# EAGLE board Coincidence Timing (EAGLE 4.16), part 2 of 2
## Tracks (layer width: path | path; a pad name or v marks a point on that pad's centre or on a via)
+1.2V  (via drill 0.51)
  Top 0.178: 111.12,40.64 IC15.2 | IC16.81 v97.41,91.31 97.41,91.19 97.79,90.81 97.79,85.98 99.44,85.98 | v80.77,91.31 80.83,91 IC16.109 82.68,91.06 82.68,91.19 84.2,91.19 | v80.77,83.69 80.96,83.5 IC16.124 85.03,83.5 85.6,82.93 | v80.77,79.76 81.03,79.76 81.28,80.01 IC16.131 84.84,80.01 85.6,80.77 85.6,82.93 | v104.65,73.28 103.39,73.28 IC16.37 102.62,73.41 102.62,73.28 101.09,73.28 | v104.65,80.14 104.52,80.01 IC16.50 | v104.65,86.11 104.65,85.98 103.19,85.98 IC16.62 102.49,85.98 99.44,85.98 | 84.2,91.19 84.33,91.31 84.33,92.08 IC16.107 | 84.2,91.19 84.33,91.06 84.33,89.53 86.74,87.12 86.74,82.93 85.6,82.93 | 101.09,73.28 100.97,73.15 100.97,72.39 IC16.35 100.97,71.12 100.97,69.72 v100.46,69.22 100.71,68.83 105.79,63.75 105.79,52.58 C85.+ | 101.09,73.28 99.44,74.93 99.44,85.98 | IC16.26 96.41,70.63 v96.14,70.36
  Top 0.508: IC15.2 C82.2 | 106.43,51.56 C85.+ 106.43,50.55
  Top 0.635: 107.7,40.64 111.12,40.64 | 106.43,47.12 106.43,50.55
  Bottom 0.178: C83.2 79.5,80.01 79.63,79.88 v80.77,79.76 | C79.2 105.45,73.28 v104.65,73.28 104.27,73.53 103.63,73.53 102.74,74.42 100.58,74.42 100.58,78.23 102.23,79.88 104.27,79.88 v104.65,80.14 C78.2 | C80.2 105.58,86.11 v104.65,86.11 | v100.46,69.22 96.9,69.22 C77.2 96.52,69.98 v96.14,70.36 | C74.2 79.63,91.06 79.88,91.31 v80.77,91.31 81.15,90.81 86.74,90.81 87.76,89.79 97.03,89.79 C72.2 v97.41,91.31 | C76.2 79.76,83.44 80.01,83.69 v80.77,83.69
  pour Top (isolate 0.381): 76.2,33.02 76.2,48.26 107.95,48.26 107.95,33.02
+3.3V  (via drill 0.51)
  Top 0.178: R10.1 32.89,100.2 34.29,100.2 34.92,100.84 36.7,100.84 R14.1 v37.85,100.2 | 48.01,25.65 C81.2 | R42.1 32.38,62.61 32.89,62.1 34.29,62.1 34.92,62.74 36.7,62.74 R46.1 v37.85,62.1 | C5.2 IC2.8 19.68,84.07 19.81,84.2 v21.08,84.2 | C34.2 19.18,73.28 IC8.8 19.56,73.41 19.68,73.53 v21.08,73.53 | R12.1 v31.37,96.77 | R44.1 v31.37,58.67 | 29.34,59.56 L13.1 29.46,59.56 v29.46,58.42 | 29.34,59.56 29.46,59.69 | L10.2 v18.92,53.85 | L1.2 v18.92,92.33 | 24.98,95 L2.1 v26.16,94.87 | 29.34,59.56 29.34,59.44 | L3.1 33.62,89.95 v33.53,90.04 | L12.1 35.05,51.82 34.92,51.94 v33.53,51.94 | R40.1 v31.24,67.31 | R8.1 v31.11,105.41 | 25.69,107.61 L5.1 25.65,107.31 25.78,107.44 v24.38,107.44 | L15.1 v43.43,69.72 | 41.78,107.82 L6.1 v43.31,107.82 | L4.1 29.46,97.66 v29.46,96.52 | L11.1 v26.16,56.77 | L14.1 25.57,69.34 v24.38,69.34 | R57.2 v54.48,54.23 | R59.2 v62.1,54.23 | R27.2 v62.1,92.33 | R25.2 v54.48,92.33 | 58.67,108.58 58.67,108.71 58.65,108.71 IC6.32 58.65,108.58 58.67,108.58 | 58.67,108.58 v58.67,107.44 | 58.67,70.61 v58.67,69.34 | 63.75,66.29 63.7,66.29 IC12.22 63.75,66.18 63.75,66.17 63.7,66.22 IC12.23 63.96,66.8 v65.02,66.8 | IC6.22 63.63,104.28 63.63,104.27 63.7,104.34 IC6.23 63.75,104.93 63.75,104.9 63.88,104.78 v65.02,104.78 | 58.67,108.58 C29.2 | 58.67,70.61 58.65,70.61 IC12.32 | 58.67,70.61 C56.2 | IC6.13 v62.99,97.28 | IC12.13 v62.99,59.18 | 98.55,123.95 IC17.18 | 98.55,123.95 C88.2 | 98.55,123.95 96.52,123.95 96.01,123.44 IC17.20 92.91,122.12 91.69,120.9 91.69,120.14 | 89.15,119.38 89.09,119.38 IC18.6 89.53,119.51 90.17,120.14 91.69,120.14 | C90.2 89.11,119.42 89.15,119.38 | 91.69,120.14 91.69,120.23 R74.2 | 89.15,119.38 87.63,119.38 87.12,118.87 87.12,113.54 87.88,112.78 91.69,112.78 91.69,112.69 R76.2 91.57,111.63 91.69,111.51 v91.69,111.38
  Top 0.178: 99.44,92.78 IC16.77 99.44,92.08 99.44,91.57 v99.57,91.19 99.82,90.81 99.82,88.01 | 94.61,97.79 R68.2 v94.61,98.93 | IC16.84 95.91,91.29 v95.76,90.93 | v97.92,98.93 R67.2 | v86.87,94.36 86.87,94.23 86.91,94.19 IC16.102 | IC16.138 82.11,76.45 v80.77,76.45 | v80.77,87.76 80.9,87.5 IC16.116 | 82.12,82.04 IC16.127 83.02,82 v83.57,82.55 | IC16.5 85.85,71.69 v85.85,70.36 | C61.2 v94.87,70.36 94.87,71.71 IC16.23 95,72.39 95,73.28 97.66,73.28 97.79,73.15 97.79,72.64 97.92,72.64 97.92,72.39 IC16.29 | C86.2 125.22,72.39 MOD1.2-31 | 105.79,77.98 103.89,77.98 IC16.46 | 105.79,77.98 108.33,77.98 v108.71,78.36 109.6,78.36 110.24,77.72 110.24,75.44 v111.63,74.04 | 105.79,77.98 105.79,81.92 105.7,82 IC16.54 102.49,82.04 101.6,82.04 v101.6,82.42 | C63.1 IC13.8 IC13.7 87.76,62.61 87.76,62.23 87.5,62.23 87.5,62.1 85.72,62.1 85.72,61.98 v85.47,61.59 IC13.3 | R66.2B 97.79,57.15 97.54,57.15 R66.3B 97.03,56.64 v97.03,55.88 | 99.82,88.01 102.49,88.01 IC16.66 | v100.08,58.67 100.08,58.93 99.82,59.18 99.82,61.21 J3.4 | v90.42,94.23 v90.41,94.22 IC16.95 90.41,92.71 90.42,92.71 v90.42,91.19 | R70.2 v92.58,98.93 v89.41,98.93 | 99.82,88.01 99.82,87.88 v99.06,87.12
  Top 0.635: C84.+ 57.4,24.38 56.13,25.65 48.01,25.65 IC14.2 | v94.61,82.68 v94.61,86.36 | v87.88,84.84 v87.88,86.49
  Bottom 0.178: C68.2 99.44,91.06 arc-90 v99.57,91.19 99.31,91.57 99.31,92.33 95.25,92.33 | v95.76,90.93 95,90.93 | v97.92,98.93 94.74,98.93 94.61,98.81 | v108.71,78.36 108.2,78.87 106.17,78.87 106.17,78.36 C60.2 | v111.63,74.04 112.39,73.28 123.95,73.28 123.95,72.9 MOD1.2-31 | 101.6,82.04 95.25,82.04 v94.61,82.68 | 101.6,82.04 105.28,82.04 C59.2 | 95.25,55.88 v97.03,55.88 99.82,58.67 v100.08,58.67 | 95.25,59.82 99.69,59.82 J3.4 | 101.6,82.04 v101.6,82.42 | v99.06,87.12 98.93,87.25 95.12,87.25 95.12,86.87 v94.61,86.36
  Bottom 0.635: IC14.2 45.97,25.65 48.26,27.94 48.26,50.8
  pour Bottom: 17.78,114.3 17.78,49.53 95.25,49.53 95.25,106.68 107.95,106.68 107.95,124.46 82.55,124.46 82.55,114.3
+5V  (via drill 0.51, 0.71)
  Top 0.178: 48.01,28.19 C73.2 | L8.2 53.59,114.05 70.87,114.05 v70.87,109.73 | v70.87,95.5 70.61,95.25 L7.2 | 53.59,74.17 L17.2 v53.59,77.98 | v70.87,57.15 L16.2 | v68.33,77.98 v60.2,77.98 | FAN+.TP 12.45,11.43 C65.+ 12.45,12.45 20.32,20.32 29.21,20.32 29.21,21.34 32,24.13 NTC+.TP | 122.05,111 121.92,111 C89.2 122.05,111.76 122.17,111.51 122.83,110.84 | R73.2 127.51,113.79 R72.CCW | R72.CCW 127.25,113.79 | DIS.2 122.83,110.84 | 122.83,110.84 122.83,115.22 123.7,116.08 126.49,116.08 127.25,115.32 R72.CCW
  Top 0.508: IC15.3 C75.2
  Top 0.635: 64.77,22.86 63.5,22.86 C70.+ | 64.77,22.86 F1.1A | C70.+ 62.23,25.4 59.44,28.19 48.01,28.19 IC14.3 | v73.66,95.5 73.66,77.98 v68.33,77.98 | v70.87,69.85 70.1,69.85 v68.33,71.63 | v70.87,42.93 v70.87,51.05 | v112.01,45.47 IC15.3 | v83.06,104.65 83.82,103.89 85.09,103.89 87.38,106.17 89.15,106.17 92.96,102.36 v102.11,102.36 | DIS.2 122.83,106.93 122.94,106.93 120.9,104.9 118.62,104.9 116.08,102.36 v112.52,102.36 | v70.87,33.27 63.12,25.53 63.12,24.89 62.36,24.13 C70.+ | 64.77,22.86 64.77,18.54 62.48,16.26 62.48,14.22 D1.2 64.9,14.22
  Bottom 0.178: v70.87,95.5 v70.87,109.73 | v60.2,77.98 v53.59,77.98 | 42.93,27.94 43.18,27.94 | 42.93,27.94 IC14.3 | 42.93,27.94 39.37,27.94 36.7,25.27 31.88,25.27 31.88,24.13 NTC+.TP
  Bottom 0.508: 70.61,42.93 v70.87,42.93 71.12,42.93
  Bottom 0.635: v70.87,95.5 v73.66,95.5 v83.06,104.65 | v70.87,69.85 v70.87,57.15 v70.87,51.05 | v68.33,71.63 v68.33,77.98 | v70.87,33.27 v70.87,42.93 | v112.01,45.47 112.01,46.48 71.12,46.48 71.12,42.93 | v102.11,102.36 v112.52,102.36
/LATCH_EN  (via drill 0.51)
  Top 0.178: R7.2 40.39,94.65 v40.39,87.38 | v66.29,82.8 68.83,82.8 v68.83,88.9 | R39.2 42.2,56.68 v45.59,60.07 | v39.88,72.39 v39.88,75.69 | v45.59,70.1 v43.31,72.39 | v45.59,65.53 v45.59,68.07 | v45.47,82.8 v43.43,82.8 v52.32,82.8 | v101.73,91.31 101.73,89.41 102.49,89.41 IC16.69
  Bottom 0.178: v40.39,87.38 40.39,82.8 v43.43,82.8 | v52.32,82.8 v66.29,82.8 | v68.83,88.9 71.63,88.9 83.57,100.58 v85.34,100.58 85.72,100.33 89.15,100.33 93.22,96.27 100.97,96.27 100.97,92.08 v101.73,91.31 | v45.59,60.07 v45.59,65.53 | v43.31,72.39 v39.88,72.39 | v45.59,68.07 v45.59,70.1 | v39.88,75.69 39.88,77.22 v45.47,82.8
AGND  (via drill 0.51, 0.71, 1.07)
  Top 0.178: 26.54,65.44 IC10.15 26.44,65.46 26.44,65.63 26.42,65.66 26.42,62.1 | 22.35,61.47 22.35,62.23 22.38,62.26 IC7.13 | 20.07,59.94 20.95,59.94 | IC7.15 21.39,62.28 21.39,62.13 21.34,62.08 21.34,61.47 20.19,61.47 | IC1.4 20.09,98.04 | IC1.13 22.35,100.35 22.35,99.57 22.23,99.69 21.34,99.69 21.34,100.33 IC1.15 | IC1.1 20.83,99.57 | 20.83,98.04 20.07,98.04 IC1.4 | 26.42,100.2 26.42,103.76 26.44,103.73 IC4.15 | 26.92,100.2 26.92,103.76 26.95,103.73 IC4.14 | 26.92,62.1 26.92,65.66 26.95,65.63 26.95,65.46 IC10.14
  Bottom 0.178: C35.2 21.3,67.27 v21.21,67.18 | C6.2 21.3,105.37 v21.21,105.28 | C10.2 24.26,103.72 v24.26,105.03 24.26,106.01 C12.2 | C40.1 24.51,66.55 arc90 v24.26,66.8 24.26,67.91 C42.1 | C27.1 64.17,107.66 v64.01,107.82 | C57.1 64.17,69.56 v64.01,69.72 | C52.1 55.08,63.59 v55.88,64.39 56.68,63.59 C50.1 | C51.1 59.91,63.59 v60.83,64.52 61.76,63.59 C58.1 | C21.1 55.08,101.69 v55.88,102.49 56.68,101.69 C22.1 | C23.1 60.03,101.69 v60.96,102.62 61.89,101.69 C28.1 | C25.1 v57.78,104.9 | C53.1 v57.78,66.8 | C69.1 90.26,97.28 v88.9,97.28 88.86,97.24 C71.1 | C74.1 77.89,89.32 77.85,89.28 v77.85,89.41 77.89,89.37 C67.1 | 77.98,76.45 C64.1 77.85,76.45 77.85,80.01 C83.1 77.89,83.4 77.85,83.44 | v87,67.44 86.23,67.44 C62.1 | 77.85,83.44 v76.58,83.44 | C66.1 84.71,83.69 85.34,83.06 | 77.85,83.44 C76.1
  Bottom 0.635: v86.36,82.17 v85.98,83.69 85.34,83.06 v84.84,82.55 86.36,82.04
  other vias: 12.95,101.6 12.95,63.5 45.72,30.48 50.8,30.48 50.8,49.02 45.72,49.02 109.09,80.14 108.97,94.74 110.49,117.09 97.03,105.16 114.81,38.1 68.33,38.61 50.8,21.59 7.62,81.03 32.26,120.9 69.34,122.43 95,132.08 144.53,84.58 147.07,26.67 73.41,38.61 101.22,88.77 100.97,87.25 104.78,87.38 96.01,78.74 100.2,85.22 102.49,71.75 99.95,73.15 101.35,80.14 110.87,85.98 115.44,85.98 111.12,82.68 108.97,81.79
  pour Top (rank 2): 0,0 96.52,0 96.52,13.97 166.88,13.97 166.88,140.72 0,140.72
  pour Bottom (rank 2): 0,0 0,140.72 166.88,140.72 166.88,0
ARABBIT0  (via drill 0.51)
  Top 0.178: v108.71,88.01 108.71,84.96 103.89,84.96 IC16.60 | v119.51,89.28 124.21,89.28 124.21,88.9 MOD1.2-15
  Bottom 0.178: v108.71,88.01 109.98,89.28 v119.51,89.28
ARABBIT1  (via drill 0.51)
  Top 0.178: IC16.59 103.89,84.45 111.38,84.45 v114.94,88.01
  Bottom 0.178: v114.94,88.01 115.44,88.52 119.89,88.52 121.28,89.92 122.05,89.92 MOD1.2-14
ARABBIT2  (via drill 0.51)
  Top 0.178: v116.71,90.04 115.7,89.03 115.7,87.63 112.14,84.07 103.89,84.07 IC16.58
  Bottom 0.178: v116.71,90.04 117.98,91.31 124.21,91.31 124.21,90.93 MOD1.2-13
CAL_HI/LO  (via drill 0.51)
  Top 0.178: IC5.8 39.37,102.62 39.12,102.36 39.12,101.35 39.75,100.71 40.13,100.71 v41.91,98.93 | v41.91,86.49 v41.91,93.09 | v44.45,83.57 v53.34,83.57 | v67.31,83.57 68.07,83.57 v68.07,87.88 | IC11.8 38.99,64.52 v38.99,67.06 | 39.12,74.93 v39.12,74.8 v39.12,71.37 | IC16.144 80.61,73.5 v80.52,73.41 | v67.31,76.45 v69.34,76.45
  Bottom 0.178: v41.91,93.09 v41.91,98.93 | v41.91,86.49 41.91,83.57 v44.45,83.57 44.45,82.68 39.12,77.34 v39.12,74.8 | v53.34,83.57 v67.31,83.57 v67.31,76.45 | v68.07,87.88 71.37,87.88 83.31,99.57 v84.58,99.57 | v38.99,67.06 39.12,67.06 v39.12,71.37 | v80.52,73.41 72.39,73.41 v69.34,76.45
CALIBRATE  (via drill 0.51)
  Top 0.178: R49.1 37.17,68.58 v38.35,68.58 | v38.35,78.99 v47.24,78.99 | v72.64,93.98 v72.64,78.99 v61.21,78.99 | R17.1 38.44,106.77 v38.61,106.93 | v38.61,111.25 38.61,112.78 v40.39,114.55 | v38.35,72.39 v38.35,75.69 | IC16.143 81.19,74 81.03,74.17 v79.5,74.17 | v84.33,105.16 84.33,105.92 v79.5,110.74
  Bottom 0.178: v47.24,78.99 v61.21,78.99 | v72.64,93.98 73.41,93.98 84.33,104.65 v84.33,105.16 | v38.61,111.25 v38.61,106.93 | v38.35,75.69 v38.35,78.99 | v38.35,68.58 v38.35,72.39 | v40.39,114.55 75.69,114.55 v79.5,110.74 | v72.64,78.99 72.64,74.17 v79.5,74.17
CLK+
  Top 0.178: IC17.7 103.63,101.6 arc-90 103.12,101.09 93.85,101.09 arc90 93.6,100.84 93.6,96.39 arc-90 93.26,96.05 R70.1 | R70.1 92.58,96.01 92.46,96.01 92.46,92.8 IC16.91 | R71.2 91.31,96.01 92.54,96.01 R70.1
CLK-
  Top 0.178: IC16.90 92.91,94.44 arc-90 93.22,94.74 94.23,94.74 arc90 94.49,95 94.49,96.01 arc-180 94.49,96.05 R68.1 94.74,96.05 94.74,96.01 94.78,96.05 R69.2 96.43,96.05 arc90 96.77,96.39 96.77,99.82 arc-90 97.28,100.33 103.69,100.33 arc90 104.9,101.54 IC17.8
CLKA+
  Top 0.178: C17.1 59.18,92.33 arc180 R27.1 arc90 59.18,92.29 59.18,90.68 arc180 R28.2 arc-90 59.44,90.46 TP1A.TP
CLKA-
  Top 0.178: 57.4,92.33 arc-180 R25.1 arc180 57.4,92.33 | 57.4,92.33 C18.1 | 57.4,92.33 57.4,90.72 arc-90 R26.2 arc90 57.15,90.46 TP2A.TP
CLKB+
  Top 0.178: R59.1 59.31,54.23 59.31,55.54 arc90 C46.1 | R59.1 59.18,54.23 arc-180 R59.1 | R60.2 59.31,52.58 59.31,54.14 arc90 R59.1 | R60.2 59.18,52.58 arc-180 R60.2 | R60.2 arc-90 59.44,52.36 TP3A.TP
CLKB-
  Top 0.178: C47.1 57.4,54.23 arc-180 R57.1 arc-90 57.4,54.19 57.4,52.58 arc-180 R58.2 arc90 57.15,52.36 TP4A.TP
DA0  (via drill 0.51)
  Top 0.178: v69.22,111.76 65.79,111.76 R29.1B | v105.66,109.22 105.66,91.69 104.52,90.55 103.89,90.55 IC16.71
  Bottom 0.178: v69.22,111.76 76.83,111.76 78.99,109.6 92.71,109.6 93.34,110.24 104.65,110.24 v105.66,109.22
DA1  (via drill 0.51)
  Top 0.178: v70.1,111 65.79,111 R29.2B | v102.74,97.41 102.74,91.06 IC16.72
  Bottom 0.178: v70.1,111 70.23,110.87 77.09,110.87 80.9,107.06 88.65,107.06 94.87,100.84 99.31,100.84 v102.74,97.41
DA2  (via drill 0.51)
  Top 0.178: v79.63,107.19 71.75,107.19 69.72,109.22 69.72,110.24 65.79,110.24 R29.3B | v101.35,97.66 101.35,93.47 IC16.73
  Bottom 0.178: v79.63,107.19 80.14,106.68 88.52,106.68 94.74,100.46 98.55,100.46 v101.35,97.66
DA3  (via drill 0.51)
  Top 0.178: v72.01,106.43 69.34,109.09 69.34,109.35 65.79,109.35 R29.4B | v99.06,97.41 100.97,95.5 100.97,93.47 IC16.74
  Bottom 0.178: v72.01,106.43 72.14,106.3 88.39,106.3 94.61,100.08 98.42,100.08 99.06,99.44 v99.06,97.41
DA4  (via drill 0.51)
  Top 0.178: v81.92,92.84 81.92,93.85 77.47,98.3 77.47,105.66 70.1,105.66 R30.1B | v100.2,94.23 100.33,94.11 100.33,93.47 IC16.75
  Bottom 0.178: v81.92,92.84 82.3,93.22 99.19,93.22 v100.2,94.23
DA5  (via drill 0.51)
  Top 0.178: v81.03,93.6 77.09,97.54 77.09,104.9 70.1,104.9 R30.2B | v89.28,94.23 89.41,94.23 89.41,93.47 IC16.97
  Bottom 0.178: v81.03,93.6 88.65,93.6 v89.28,94.23
DA6  (via drill 0.51)
  Top 0.178: v76.33,104.14 70.1,104.14 R30.3B | v79.63,102.87 87.12,95.38 87.88,95.38 87.88,93.47 IC16.100
  Bottom 0.178: v76.33,104.14 77.6,102.87 v79.63,102.87
DA7  (via drill 0.51)
  Top 0.178: v73.41,103.25 70.1,103.25 R30.4B | v78.23,101.35 83.06,96.52 v83.06,92.33 | v87.38,91.31 87.5,91.44 87.5,92.08 IC16.101
  Bottom 0.178: v73.41,103.25 75.31,101.35 v78.23,101.35 | v83.06,92.33 84.07,91.31 v87.38,91.31
DA8  (via drill 0.51)
  Top 0.178: v78.99,89.53 74.93,93.6 74.93,98.68 68.83,98.68 68.83,101.47 69.22,101.47 R31.1B | v85.09,89.92 86.36,91.19 86.36,92.08 IC16.103
  Bottom 0.178: v78.99,89.53 79.38,89.92 v85.09,89.92
DA9  (via drill 0.51)
  Top 0.178: v79.12,94.36 76.71,96.77 76.71,100.84 70.1,100.84 R31.2B | v85.72,94.36 85.85,94.23 85.85,93.47 IC16.104
  Bottom 0.178: v79.12,94.36 v85.72,94.36
DA10
  Top 0.178: R31.3B 70.1,100.08 75.69,100.08 75.69,94.49 80.64,89.53 81.53,89.53 IC16.112
DA11
  Top 0.178: R31.4B 70.1,99.19 75.31,99.19 75.31,94.36 80.64,89.03 81.53,89.03 IC16.113
DAC-A  (via drill 0.51)
  Top 0.178: IC2.3 28.45,86.61 28.45,82.04 v33.53,82.04 | v42.42,82.04 v51.31,82.04 | v65.28,82.04 69.6,82.04 v69.6,89.92
  Bottom 0.178: v33.53,82.04 v42.42,82.04 | v51.31,82.04 v65.28,82.04 65.53,81.66 65.53,72.64 67.82,70.36 68.83,70.36 69.6,71.12 72.14,71.12 72.14,66.42 79.12,59.44 116.71,59.44 132.59,75.31 160.91,75.31 160.91,75.69 MOD1.1-27 | v69.6,89.92 72.01,89.92 83.95,101.6 v86.11,101.6
DAC-B  (via drill 0.51)
  Top 0.178: IC8.3 v26.29,75.95 | v39.37,79.76 v48.26,79.76 | v71.88,92.96 v71.88,84.07 71.88,79.76 v62.23,79.76
  Bottom 0.178: v26.29,75.95 28.83,79.76 v39.37,79.76 | v48.26,79.76 v62.23,79.76 | v71.88,92.96 73.15,92.96 84.96,104.52 v88.39,104.65 | v71.88,84.07 72.26,84.45 81.28,84.45 81.79,83.95 81.79,82.8 82.8,81.79 83.95,81.79 84.33,81.41 84.33,76.83 87,74.17 97.54,74.17 97.54,70.1 98.04,69.6 98.81,69.6 99.19,69.98 100.84,69.98 101.98,68.83 125.6,68.83 132.46,75.69 158.88,75.69 MOD1.1-28
DAC-CLK  (via drill 0.51)
  Top 0.178: IC8.1 27.43,73.41 27.43,80.52 | 27.43,80.52 27.43,84.07 IC2.1 | v31.5,80.52 27.43,80.52 | v49.28,80.52 v40.39,80.52 | v71.12,91.95 71.12,80.52 v63.25,80.52 | v81.28,107.82 81.79,107.31 81.79,104.14 83.06,102.87 85.85,102.87 85.85,103.25 86.49,103.89 87.25,103.89 v87.63,103.63
  Bottom 0.178: v40.39,80.52 v31.5,80.52 | v63.25,80.52 v49.28,80.52 | v71.12,91.95 72.77,91.95 84.71,103.63 v87.63,103.63 | v81.28,107.82 88.39,107.82 89.03,107.19 101.22,107.19 102.49,108.46 162.94,108.46 162.94,85.09 162.81,84.96 162.18,84.96 MOD1.1-19
DAC-D  (via drill 0.51)
  Top 0.178: IC8.2 23.11,74.68 22.61,75.18 22.61,84.71 23.24,85.34 IC2.2 27.94,85.34 27.94,81.28 v32.51,81.28 | v41.4,81.28 v50.29,81.28 | v64.26,81.28 70.36,81.28 v70.36,90.93 | v137.29,85.98 125.98,97.28 v106.43,97.28
  Bottom 0.178: v50.29,81.28 v64.26,81.28 | v70.36,90.93 72.39,90.93 84.33,102.62 v86.87,102.62 87.25,102.36 87.88,102.36 93.6,96.65 105.79,96.65 v106.43,97.28 | v137.29,85.98 144.4,85.98 145.03,85.34 160.91,85.34 160.91,85.72 MOD1.1-17 | v32.51,81.28 v41.4,81.28 v32.51,81.28
DATAREADY  (via drill 0.51)
  Top 0.178: v104.78,88.52 103.89,88.52 IC16.67
  Bottom 0.178: v104.78,88.52 106.05,87.25 115.57,87.25 116.33,86.49 122.05,86.49 MOD1.2-18
DB0  (via drill 0.51)
  Top 0.178: v65.79,86.36 58.67,79.25 58.67,76.45 63.25,76.45 64.9,74.8 64.9,74.04 R61.1B | IC16.114 79.48,88.5 77.34,86.36 v75.82,86.36
  Bottom 0.178: v65.79,86.36 v75.82,86.36
DB1  (via drill 0.51)
  Top 0.178: v65.41,84.84 59.05,78.49 59.05,76.83 64.01,76.83 66.55,74.3 66.55,73.03 65.79,73.03 R61.2B | v84.45,85.09 84.45,87.38 83.83,88 IC16.115
  Bottom 0.178: v65.41,84.84 84.33,84.84 v84.45,85.09
DB2
  Top 0.178: 74.3,78.23 74.3,77.34 71.75,77.34 66.67,72.26 65.79,72.26 R61.3B | 74.3,78.23 74.3,78.36 | IC16.118 81.53,86.49 80.77,86.49 74.3,80.01 74.3,78.23
DB3
  Top 0.178: R61.4B 65.79,71.5 67.06,71.5 67.06,72.14 71.88,76.96 74.68,76.96 74.68,79.88 80.77,85.98 81.53,85.98 IC16.119
DB4
  Top 0.178: R62.1B 70.1,67.69 70.36,67.69 71.88,69.22 71.88,76.45 72.01,76.58 75.06,76.58 75.06,79.76 80.26,84.96 81.53,84.96 IC16.121
DB5
  Top 0.178: R62.2B 70.1,66.8 70.36,66.8 72.26,68.71 72.26,76.2 75.44,76.2 75.44,79.63 80.26,84.45 81.53,84.45 IC16.122
DB6
  Top 0.178: R62.3B 69.6,66.02 69.6,66.04 70.48,66.04 72.64,68.2 72.64,75.82 75.82,75.82 75.82,79.5 79.25,82.94 81.42,82.94 81.47,83 IC16.125 | IC16.125 | IC16.125
DB7
  Top 0.178: IC16.126 79.33,82.5 76.2,79.38 76.2,75.44 73.03,75.44 73.03,67.82 70.48,65.28 69.63,65.28 | 69.63,65.28 69.6,65.28 | R62.4B 69.63,65.28
DB8  (via drill 0.51)
  Top 0.178: v73.91,65.79 73.91,63.63 70.1,63.63 R63.1B | IC16.129 80.88,81 v80.77,80.9
  Bottom 0.178: v73.91,65.79 80.39,72.26 81.03,72.26 81.92,73.15 81.92,80.9 v80.77,80.9
DB9
  Top 0.178: R63.2B 70.1,62.74 76.45,62.74 76.45,74.42 81.03,79 IC16.133
DB10  (via drill 0.51)
  Top 0.178: v77.22,67.44 77.22,61.98 70.1,61.98 R63.3B | v83.57,78.49 82.8,78.49 IC16.134
  Bottom 0.178: v77.22,67.44 83.57,73.79 v83.57,78.49
DB11
  Top 0.178: R63.4B 70.1,61.21 77.98,61.21 77.98,75.44 80.52,77.98 81.53,77.98 IC16.135
DRABBIT0  (via drill 0.51)
  Top 0.178: IC16.57 103.89,83.57 112.65,83.57 v112.78,83.44
  Bottom 0.178: v112.78,83.44 133.35,83.19 139.06,88.9 157.23,88.9 158.24,89.92 158.88,89.92 MOD1.1-14
DRABBIT1  (via drill 0.51)
  Top 0.178: IC16.55 103.89,82.55 109.73,82.55 110.49,81.79 114.68,81.79 116.71,83.82 v116.71,87.25
  Bottom 0.178: v116.71,87.25 117.6,88.14 120.14,88.14 121.28,89.28 156.21,89.28 158.24,91.31 161.16,91.31 161.16,90.93 MOD1.1-13
DRABBIT2  (via drill 0.51)
  Top 0.178: v147.07,81.28 157.73,91.95 158.88,91.95 MOD1.1-12 | IC16.53 101.95,81.5 v101.73,81.28
  Bottom 0.178: v101.73,81.28 101.98,81.03 121.03,81.03 121.28,81.28 v147.07,81.28
DRABBIT3  (via drill 0.51)
  Top 0.178: v104.65,78.99 105.16,78.99 105.41,79.25 105.41,81.03 103.89,81.03 IC16.52 | v144.27,77.34 158.24,91.31 161.16,91.31 161.16,91.69 MOD1.1-11
  Bottom 0.178: v104.65,78.99 104.14,78.49 101.35,78.49 100.97,78.11 100.97,76.33 120.27,76.33 121.28,77.34 v144.27,77.34
DRABBIT4  (via drill 0.51)
  Top 0.178: v125.98,85.34 125.98,93.98 125.22,93.98 MOD1.2-9 | IC16.48 102.49,78.99 100.46,78.99 100.46,83.69 100.97,84.2 v101.47,84.2
  Bottom 0.178: v101.47,84.2 101.73,84.33 120.27,84.33 121.28,85.34 v125.98,85.34
DRABBIT5  (via drill 0.51)
  Top 0.178: v101.73,77.72 101.73,78.49 102.49,78.49 IC16.47 | v113.67,80.26 117.47,84.07 117.47,90.17 121.28,93.98 122.05,93.98 MOD1.2-10
  Bottom 0.178: v101.73,77.72 102.74,76.71 110.11,76.71 v113.67,80.26
DRABBIT6
  Top 0.178: IC16.45 103.89,77.6 109.6,77.6 109.86,77.34 109.86,74.68 111.25,73.28 117.22,73.28 117.22,81.03 118.36,82.17 118.36,89.28 120.4,91.31 124.21,91.31 124.21,91.69 MOD1.2-11
DRABBIT7  (via drill 0.51)
  Top 0.178: v109.09,75.56 109.09,77.09 103.89,77.09 IC16.44 | v111.25,75.56 117.98,82.3 117.98,89.41 120.52,91.95 122.05,91.95 MOD1.2-12
  Bottom 0.178: v109.09,75.56 v111.25,75.56
DRABBIT8
  Top 0.178: IC16.43 103.89,76.58 108.33,76.58 108.33,75.18 114.68,68.83 150.62,68.83 150.62,73.66 158.24,81.28 161.16,81.28 161.16,80.9 MOD1.1-23
DRABBIT9
  Top 0.178: IC16.42 103.89,76.07 107.95,76.07 107.95,75.06 114.55,68.45 151,68.45 151,72.64 158.24,79.88 158.88,79.88 MOD1.1-24
DRABBIT10
  Top 0.178: IC16.41 103.89,75.56 107.57,75.56 107.57,74.93 117.22,65.28 162.94,65.28 162.94,77.85 162.81,77.98 162.18,77.98 MOD1.1-25
DRABBIT11  (via drill 0.51)
  Top 0.178: v106.81,74.8 106.81,74.93 103.89,74.93 IC16.40
  Bottom 0.178: v106.81,74.8 120.78,74.8 121.28,75.31 131.57,75.31 132.84,76.58 156.84,76.58 158.24,77.98 158.88,77.98 MOD1.1-26
N$1
  Top 0.178: IC1.3 18.3,98.57 17.78,98.04 17.74,98.04 C1.2 17.49,95.59 17.53,95.25 17.53,95.21 R1.1
N$2
  Top 0.178: IC1.2 20.32,99.06 | IC1.2 | J1.CONDUCTOR IC1.2
N$3
  Top 0.178: R1.2 17.14,88.65 16.51,88.01 14.61,88.01 14.61,85.34 19.18,85.34 19.3,85.47 IC2.7
N$4
  Top 0.178: IC4.10 31.1,101.74 arc-90 31.37,101.47 31.37,99.95 arc90 31.62,99.69 35.05,99.69 | 35.05,99.69 arc-90 35.31,99.31 35.31,99.19 | IC3.3 35.31,99.19 | 35.31,99.19 R15.1 | 35.05,99.69 35.18,99.69 arc90 35.43,99.95 arc-90 35.56,100.08 R14.2
N$5  (via drill 0.51)
  Top 0.178: 27.69,98.93 C11.2 | 27.69,98.93 27.73,98.89 27.69,98.86 27.69,97.66 L4.2 27.69,97.62 v27.69,96.5 | 27.43,100.58 27.45,100.58 IC4.8 27.43,100.46 27.43,99.19 27.69,98.93 | 25.91,100.44 arc-180 25.91,100.46 | 25.91,100.44 IC4.5 | IC4.2 24.65,102.24 arc90 24.38,101.98 24.38,100.46 arc90 24.51,100.33 v24.56,100.33 | v26.04,98.91 25.91,99.06 25.91,100.44 | v27.69,96.5 27.69,96.39 | v27.69,96.5 27.69,96.52
  Bottom 0.178: v24.56,100.33 25.78,98.93 v26.04,98.91 27.69,97.26 v27.69,96.5 | v24.56,100.33 24.64,100.33 24.64,101.64 C10.1 | v24.56,100.33 24.51,100.33
N$6
  Top 0.178: IC1.11 23.5,99.07 arc90 23.82,99.39 23.82,102.49 arc-90 24.08,102.74 IC4.1
N$7
  Top 0.178: R2.2 21.21,101.85 21.87,101.2 IC1.14
N$8  (via drill 0.51)
  Top 0.178: L1.1 18.92,95.25 19.81,96.14 | 19.81,96.14 20.32,96.14 20.45,96.01 C2.2 20.45,96.14 20.83,96.52 20.83,97.41 20.87,97.41 IC1.5 | 20.83,100.46 20.83,100.33 20.87,100.33 IC1.16 20.87,100.46 20.83,100.46 | 20.83,100.46 20.87,100.42 | v19.18,97.03 19.18,96.77 19.81,96.14 | 20.83,100.46 v19.18,100.46 19.68,100.97 C3.2
  Bottom 0.178: v19.18,97.03 v19.18,100.46
N$9
  Top 0.178: IC1.10 23.11,98.57 arc180 23.11,98.55 25.07,98.55 arc90 25.3,98.78 25.3,101.09 arc90 25.17,101.22 arc90 IC4.4
N$10
  Top 0.178: IC10.10 31.1,63.64 arc-90 31.37,63.37 31.37,61.85 arc90 31.62,61.59 35.05,61.59 | 35.05,61.59 arc-90 35.31,61.34 35.31,61.09 | 35.31,61.09 IC9.3 | 35.31,61.09 R47.1 | 35.05,61.59 35.18,61.59 arc90 R46.2
N$11  (via drill 0.51)
  Top 0.178: 23.11,98.07 23.11,98.04 | 23.11,98.07 IC1.9 23.24,98.07 23.24,98.04 | L2.2 23.28,96.1 23.24,96.14 C7.2 23.24,96.35 v23.24,97.28 | 22.37,97.28 22.35,97.28 IC1.8 22.37,97.28 | v22.73,102.11 22.89,101.96 22.89,99.85 IC1.12 | 23.11,98.07 23.24,97.94 v23.24,97.28 | v23.24,97.28 22.37,97.28
  Bottom 0.178: C6.1 v22.73,102.11 22.73,98.04 v23.24,97.28
N$12
  Top 0.178: IC4.9 30.58,101.24 arc-90 30.86,100.97 30.86,99.44 arc90 31.11,99.19 31.37,99.19 | 32.38,99.19 31.37,99.19 | 32.38,99.19 34.54,99.19 arc-90 34.8,98.93 IC3.4 | 31.37,99.19 R12.2 | R13.1 32.38,99.19
N$13  (via drill 0.51)
  Top 0.178: 27.43,103.54 IC4.13 27.43,103.5 27.43,103.63 v27.69,104.65 27.56,105.88 C13.2 27.43,106.05 | 27.43,106.05 27.43,106.17 | L5.2 27.43,107.31 27.43,106.05 | IC4.16 25.91,103.58 25.91,104.52 v25.78,104.65
  Bottom 0.178: C12.1 25.78,105.83 v25.78,104.65 v27.69,104.65
N$14
  Top 0.178: IC1.7 21.87,93.7 arc90 22.1,93.47 30.86,93.47 arc90 31.11,93.73 31.11,94.11 arc-90 31.37,94.36 32.26,94.36 arc90 32.38,94.49 R3.2 34.58,94.45 arc-90 34.8,94.23 IC3.7
N$15
  Top 0.178: R20.2 43.05,102.62 42.33,103.34 R21.2 41.78,103.38 41.53,103.63 IC5.10 40.13,105.28 C14.1 40.17,106.51 40.13,106.55 | 40.13,106.55 40.17,106.59 L6.2 36.32,107.82 35.81,107.31 R16.2 | 40.13,106.55 C15.2 | R16.2 R18.2 | R16.2 35.81,106.68
N$16
  Top 0.178: R18.1 R19.2 | R18.1 34.54,105.03 | R18.1 34.29,105.07 34.29,103.12 IC5.2
N$17
  Top 0.178: IC5.7 41.02,102.11 arc-90 41.4,101.73 arc94 41.53,101.64 R21.1 41.95,101.64 42.04,101.73 R22.1
N$18
  Top 0.178: IC1.6 21.37,93.19 arc90 21.59,92.96 32.13,92.96 arc-90 32.38,92.71 R3.1 33.82,92.75 arc90 IC3.6
N$19
  Top 0.178: R4.1 36.49,96.48 35.81,97.16 IC3.2 | R5.2 38.9,97.96 37.97,97.03 R4.1 | R4.1 37.97,96.39
N$20
  Top 0.178: R6.1 39.24,96.52 39.28,96.48 R7.1 40.51,98.68 40.39,98.81 38.35,98.81 37.59,98.04 IC3.1
N$21
  Top 0.178: R6.2 38.01,94.78 37.97,94.74 R4.2 37.97,94.23 36.96,93.22 IC3.10 C8.1 | C8.1 36.32,91.69 36.28,91.66 L3.2 35.05,91.69 35.31,91.95 IC3.8 | C8.1 36.32,91.57 36.41,91.66 C9.2
N$22
  Top 0.178: IC5.6 40.13,101.47 arc90 40.77,100.84 43.05,100.84 | 43.05,100.84 R20.1 | 43.05,100.84 arc90 43.81,100.08 R23.1
N$23
  Top 0.178: R16.1 R17.2 | R16.1 35.81,105.03 | IC5.1 35.56,103.63 35.56,105.07 R16.1
N$24
  Top 0.178: 30.1,102.74 IC4.12 | 30.1,102.74 31.11,102.74 | 31.11,102.74 34.04,102.74 34.16,102.62 IC5.3 | R9.1 30.1,102.74 | 31.11,102.74 R8.2
N$25
  Top 0.178: IC4.11 32.38,102.24 | 32.38,102.24 33.4,102.24 | 33.4,102.24 33.9,102.24 34.04,102.11 IC5.4 | 32.38,102.24 R10.2 | 33.4,102.24 R11.1
N$26
  Top 0.178: IC6.7 arc180 58.04,97.28 58.04,96.1 arc-90 C18.2
N$27
  Top 0.178: R22.2 48.64,101.73 arc-90 48.77,101.6 R24.2 50.13,101.56 arc90 50.16,101.6 C16.2 50.16,101.47 arc90 50.55,101.09 52.2,101.09 arc180 52.2,101.03 IC6.49
N$28
  Top 0.178: R23.2 48.51,100.08 arc-90 48.77,99.82 R24.1 50.13,99.86 arc-90 50.16,99.82 C16.1 50.16,99.95 arc-90 50.55,100.33 52.32,100.33 arc-180 52.3,100.33 IC6.50
N$29
  Top 0.178: IC6.8 arc180 58.67,97.28 58.67,95.97 arc90 C17.2
N$30  (via drill 0.51)
  Top 0.178: C26.2 51.31,98.17 52.2,99.06 52.2,99.08 IC6.52 52.3,99.06 52.32,99.06 52.45,98.93 v52.45,98.23 | L8.1 55.16,110.66 55.24,110.74 C24.2 55.37,108.84 55.5,108.71 55.5,108.68 | IC6.37 55.4,108.71 55.37,108.71 IC6.37 | 55.5,108.68 IC6.36 | 55.5,108.68 IC6.37 | IC6.42 53.17,105.58 53.59,105.16 v53.59,104.9 53.59,104.65 53.23,104.28 IC6.44 | 55.5,108.68 55.5,107.57 v55.37,107.44
  Bottom 0.178: 54.86,104.9 v53.59,104.9 52.45,103.76 v52.45,98.23 | 54.86,104.9 C25.2 | v55.37,107.44 55.37,105.41 54.86,104.9
N$31  (via drill 0.51)
  Top 0.178: v97.79,74.93 82.8,74.93 IC16.141 | v116.59,72.14 121.28,76.83 121.28,85.34 124.21,85.34 124.21,85.72 MOD1.2-17
  Bottom 0.178: v97.79,74.93 98.68,74.04 102.23,74.04 104.14,72.14 v116.59,72.14
N$32
  Top 0.178: 52.32,103.63 IC6.45 51.56,103.63 50.29,104.9 C19.2
N$33
  Top 0.178: C20.2 50.93,103.25 51.18,103 52.32,103 52.32,102.98 IC6.46
N$34  (via drill 0.51)
  Top 0.178: IC6.5 IC6.6 57.35,98.73 v57.28,98.81 | L7.1 61,95.59 59.94,96.65 IC6.10 59.95,98.8 v59.94,98.81 | IC6.2 54.75,98.79 v54.74,98.81
  Bottom 0.178: 57.02,99.95 C22.2 | 57.02,99.95 56.98,99.99 C21.2 v54.74,98.81 | 59.82,99.95 C23.2 | 57.02,99.95 59.82,99.95 | 57.02,99.95 57.02,99.06 v57.28,98.81 | 59.82,99.95 59.82,98.93 v59.94,98.81
N$35
  Top 0.178: IC6.30 59.95,111.51 arc-90 60.2,111.76 63.75,111.76 63.72,111.76 R29.1A
N$36
  Top 0.178: IC6.29 60.6,110.64 arc-90 60.96,111 63.75,111 63.75,111.02 R29.2A
N$37
  Top 0.178: IC6.28 61.25,110.02 arc-90 61.47,110.24 63.75,110.24 63.75,110.22 R29.3A
N$38
  Top 0.178: R29.4A arc247 63.75,109.47 62.23,109.47 arc90 61.98,109.22 61.98,108.71 arc90 IC6.27
N$39
  Top 0.178: R30.1A 67,105.72 arc-90 66.8,105.92 66.8,106.68 arc90 66.55,106.93 63.75,106.93 63.7,106.93 IC6.26
N$40
  Top 0.178: IC6.25 63.7,106.17 arc180 63.75,106.17 66.04,106.17 arc-90 66.29,105.92 66.29,105.16 arc90 66.53,104.92 R30.2A
N$41
  Top 0.178: R30.3A 66.53,104.12 arc90 66.29,103.89 66.29,103.25 arc-90 66.04,103 63.75,103 63.75,102.98 IC6.20
N$42
  Top 0.178: R30.4A 67,103.32 arc90 66.8,103.12 66.8,102.62 arc-90 66.55,102.36 63.75,102.36 arc-90 63.75,102.33 IC6.19
N$43
  Top 0.178: R31.1A 68.03,101.6 68.07,101.6 arc90 67.99,101.68 IC6.18
N$44
  Top 0.178: IC6.17 66.61,101.03 arc-90 66.8,100.84 arc90 66.93,100.71 67.94,100.71 arc90 68.07,100.84 68.07,100.86 R31.2A
N$45
  Top 0.178: IC6.16 66.37,100.38 arc-90 66.55,100.2 66.55,100.08 arc90 66.67,99.95 67.82,99.95 arc90 67.94,100.08 67.94,100.06 R31.3A
N$46
  Top 0.178: IC6.15 66,99.73 arc-90 66.17,99.57 66.17,99.44 arc90 66.29,99.31 67.94,99.31 67.94,99.26 R31.4A
N$47
  Top 0.178: C4.2 IC2.6
N$48
  Top 0.178: R76.1 91.44,114.39 91.44,114.3 91.53,114.39 R76.1 | R76.1 R77.2 102.45,114.39 arc90 103.63,115.57 IC17.14 103.63,122.17 | IC18.4 89.15,114.43 88.9,114.55 89.07,114.39 R76.1
N$49
  Top 0.178: IC18.5 89.09,117.09 89.15,117.09 89.66,117.6 90.17,117.6 91.06,118.49 91.57,118.49 R74.1 91.69,118.53 91.69,118.62 91.78,118.53 R75.2 92.71,118.53 arc-180 92.71,118.62 arc90 92.96,118.36 95.76,118.36 arc-90 96.52,117.6 96.52,116.59 arc90 97.28,115.82 101.6,115.82 arc90 102.36,116.59 IC17.15 102.36,122.17
N$50
  Top 0.178: IC17.13 C87.1
N$51  (via drill 0.51)
  Top 0.178: IC16.14 90.42,71.12 90.42,69.22 94.61,65.02 J3.7 | IC13.2 v87,62.87
  Bottom 0.178: v87,62.87 87.12,62.74 93.09,62.74 93.47,63.12 94.36,63.12 J3.7
N$52  (via drill 0.51)
  Top 0.178: v92.84,67.94 90.93,69.85 90.93,71.12 IC16.15 | v90.55,65.53 90.55,62.23 90.3,62.23 90.3,61.85 89.79,61.85 IC13.6
  Bottom 0.178: J3.1 101.6,64.39 100.97,64.39 99.44,65.91 94.87,65.91 v92.84,67.94 92.58,67.56 v90.55,65.53
N$53  (via drill 0.51)
  Top 0.178: v83.69,67.69 83.69,71.12 83.82,71.12 IC16.1 | IC13.5 90.68,60.33 90.68,61.85 91.44,62.61 91.44,63.5 J3.9
  Bottom 0.178: v83.69,67.69 87.63,63.75 J3.9
N$54
  Top 0.178: 84.45,68.2 84.45,64.39 IC13.1 | 84.45,68.2 84.45,71.12 IC16.2 | 84.45,68.2 89.66,68.2 93.47,64.39 93.47,61.47 93.98,61.47 J3.8
N$55  (via drill 0.51)
  Top 0.178: v98.55,73.15 98.55,82.04 96.52,84.07 96.52,91.31 96.39,91.44 96.39,92.08 IC16.83 | v98.42,70.36 99.69,69.09 J3.3 100.33,63.5 100.33,62.61 100.97,61.98 100.97,57.91 97.54,57.91 97.28,58.17 97.28,58.67 97.26,58.67 R66.3A
  Bottom 0.178: v98.55,73.15 98.55,70.36 v98.42,70.36
N$56
  Top 0.178: R66.2A 98.06,59.2 98.55,59.69 98.55,62.48 97.28,63.75 J3.5
N$57
  Top 0.178: R66.4B 96.27,57.28 95.38,57.28 95.38,59.44 96.27,60.33 96.65,60.33 96.65,60.83 J3.6 96.52,61.47 96.52,62.36 95.76,63.12 95.76,64.52 93.6,66.67 93.6,68.71 93.09,68.71 91.44,70.36 91.44,71.12 IC16.16
N$58
  Top 0.178: 96.9,92.76 IC16.82 96.91,94.94 97.98,96.01 R67.1
N$59
  Top 0.178: IC6.14 65.26,99.08 arc-90 65.53,98.81 65.53,97.79 arc90 65.79,97.54 67.56,97.54 arc-90 67.82,97.28 R32.1
N$60
  Top 0.635: F1.2A +5V_IN.TP
N$61
  Bottom 0.178: DIS.14 152.53,106.55 152.53,97.28 123.06,97.28 123.06,96.9 MOD1.2-8
N$62  (via drill 0.51)
  Top 0.178: v139.06,96.52 149.1,106.55 149.1,106.81 149.73,106.81 DIS.13
  Bottom 0.178: v139.06,96.52 125.22,96.52 MOD1.2-7
N$63
  Bottom 0.178: DIS.12 147.57,106.55 147.57,102.87 129.54,102.87 125.98,99.31 123.06,99.31 123.06,98.93 MOD1.2-6
N$64
  Top 0.178: DIS.11 144.78,106.81 144.02,106.81 144.02,106.43 136.27,98.68 125.22,98.68 MOD1.2-5
N$65
  Bottom 0.178: DIS.6 132.59,106.55 132.59,103.63 121.67,103.63 121.28,103.25 121.28,100.71 122.05,100.71 MOD1.2-4
N$66
  Top 0.178: DIS.5 129.79,106.81 129.03,106.81 129.03,103.38 125.98,100.33 125.22,100.33 MOD1.2-3
N$67
  Top 0.178: DIS.4 127.25,106.81 126.62,106.81 126.62,106.55 123.7,103.63 123.06,103.63 123.06,103 MOD1.2-2
N$68
  Top 0.178: DIS.3 125.33,106.93 125.22,106.93 125.98,107.7 R72.W
N$69
  Top 0.178: IC10.9 30.58,63.14 arc-90 30.86,62.87 30.86,61.34 arc90 31.11,61.09 31.37,61.09 | 32.38,61.09 31.37,61.09 | 32.38,61.09 34.54,61.09 arc-90 34.8,60.83 IC9.4 | 31.37,61.09 R44.2 | R45.1 32.38,61.09
N$70
  Top 0.178: DIS.15 154.81,107.31 154.05,107.31 154.05,107.7 147.96,113.79 R73.1
N$71
  Top 0.178: IC7.2 20.32,60.96 | IC7.2 | J2.CONDUCTOR IC7.2
N$72  (via drill 0.51)
  Top 0.178: v86.23,76.07 82.8,76.07 IC16.139 | v119.13,85.72 121.28,87.88 122.05,87.88 MOD1.2-16
  Bottom 0.178: v86.23,76.07 93.73,83.44 99.57,83.44 101.09,84.96 102.23,84.96 102.49,84.71 118.11,84.71 v119.13,85.72
N$73
  Top 0.178: FAN-.TP 12.45,7.62 C65.- 13.84,7.49 16.51,10.16 Q1.2
N$74
  Top 0.178: R33.1 18.03,60.2 | IC7.3 20.07,60.45 17.78,60.45 17.53,60.2 R33.1 | C30.2 17.49,58.67 17.53,58.67 R33.1
N$75
  Top 0.178: 21.84,62.1 21.87,62.1 IC7.14 21.87,62.97 21.21,63.63 R34.2
N$76  (via drill 0.51)
  Top 0.178: L10.1 18.92,57.15 19.68,57.91 | 19.68,57.91 20.32,57.91 20.45,58.04 | 20.45,58.04 C32.2 | 20.45,58.04 20.83,58.42 20.83,59.17 IC7.5 | 20.83,62.36 20.87,62.36 IC7.16 20.87,62.23 19.43,62.23 v19.3,62.36 19.3,63.37 19.68,63.75 C31.2 | v19.3,59.05 19.3,58.29 19.68,57.91
  Bottom 0.178: v19.3,59.05 v19.3,62.36
N$77  (via drill 0.51)
  Top 0.178: L11.2 23.28,58 23.24,58.04 | v22.73,64.01 22.86,63.88 22.99,63.88 22.99,61.65 IC7.12 | IC7.8 22.38,59.18 v23.24,59.18 | IC7.9 23.24,59.94 v23.24,59.18 | C36.2 23.24,58.04 | 23.24,58.04 v23.24,59.18
  Bottom 0.178: C35.1 v22.73,64.01 22.73,59.69 v23.24,59.18
N$78  (via drill 0.51)
  Top 0.178: IC10.8 27.64,62.15 27.64,60.81 27.71,60.81 C39.1 27.69,60.83 27.73,60.79 L13.2 27.69,59.52 v27.69,58.4 | IC10.5 25.91,62.36 25.91,60.94 v26.04,60.81 | IC10.2 24.65,64.14 arc90 24.38,63.88 24.38,62.36 arc90 24.51,62.23 v24.56,62.23
  Bottom 0.178: C40.2 24.51,62.23 v24.56,62.23 24.64,62.23 26.04,60.83 v26.04,60.81 26.04,60.78 27.69,59.13 v27.69,58.4 27.69,58.37
N$79  (via drill 0.51)
  Top 0.178: 27.43,65.44 IC10.13 27.56,65.56 27.56,66.42 v27.69,66.55 27.69,67.65 C41.1 27.3,67.94 27.3,69.22 L14.2 | v25.78,66.55 25.91,66.42 25.91,65.48 IC10.16
  Bottom 0.178: C42.2 25.78,67.73 v25.78,66.55 v27.69,66.55
N$80
  Top 0.178: IC7.11 23.58,60.97 arc90 23.82,61.21 23.82,64.41 arc-90 24.08,64.64 IC10.1
N$81
  Top 0.178: IC7.10 25.09,60.47 arc90 25.3,60.68 25.3,62.97 arc90 25.15,63.12 IC10.4
N$82
  Top 0.178: TP1.TP 93.85,109.35 arc-90 95,110.49 95.25,110.49 arc90 96.01,111.25 IC17.1
N$83
  Top 0.178: TP2.TP 96.14,109.6 arc-90 96.52,109.98 96.77,109.98 arc90 97.28,110.49 IC17.2
N$84
  Top 0.178: IC17.3 98.55,112.01 arc90 98.42,111.89 TP3.TP
N$85
  Top 0.178: IC7.7 21.87,55.6 arc90 22.1,55.37 30.86,55.37 arc90 31.11,55.63 31.11,56.01 arc-90 31.37,56.26 32.26,56.26 arc90 32.38,56.39 R35.2 34.58,56.35 arc-90 34.8,56.13 IC9.7
N$86
  Top 0.178: IC7.6 21.37,55.09 arc90 21.59,54.86 32.13,54.86 arc-90 32.38,54.61 R35.1 33.82,54.65 arc90 IC9.6
N$87
  Top 0.178: R36.1 36.36,58.38 35.81,58.93 IC9.2 | R37.2 38.9,59.86 37.97,58.93 R36.1 | R36.1 37.97,58.29
N$88
  Top 0.178: R38.1 39.24,58.42 39.28,58.38 R39.1 | R39.1 40.51,58.42 | IC9.1 37.47,59.94 38.23,60.71 40.51,60.71 R39.1 | R39.1 40.51,58.29
N$89
  Top 0.178: C37.1 36.36,53.55 36.32,53.59 | 36.32,53.59 C38.2 IC9.10 37.08,55.12 37.97,56.01 R36.2 37.97,56.64 38.01,56.68 R38.2 | 36.32,53.59 36.28,53.55 L12.2 35.05,53.59 35.31,53.85 IC9.8
N$90
  Top 0.178: R50.1 34.67,66.97 34.67,66.93 34.63,66.97 R50.1 | R50.1 R51.2 | R50.1 34.29,66.97 34.29,65.02 IC11.2
N$91
  Top 0.178: R49.2 35.85,66.97 35.81,66.93 R48.1 35.81,66.04 IC11.1
N$92
  Top 0.178: 30.23,64.64 IC10.12 | 30.23,64.64 31.24,64.64 | 31.24,64.64 34.16,64.64 34.29,64.52 IC11.3 | R41.1 30.23,64.64 | 31.24,64.64 R40.2
N$93
  Top 0.178: IC10.11 32.38,64.14 | 32.38,64.14 33.4,64.14 | 33.4,64.14 34.03,64.14 34.16,64.01 IC11.4 | 32.38,64.14 R42.2 | 33.4,64.14 R43.1
N$94
  Top 0.178: IC11.7 41.15,64.01 arc-90 41.4,63.75 arc90 41.66,63.54 R53.1 41.78,63.5 41.91,63.63 44.45,63.63 44.54,63.54 44.62,63.54 arc90 44.7,63.63 R54.1
N$95
  Top 0.178: IC11.6 40.13,63.12 arc90 40.51,62.74 43.05,62.74 | 43.05,62.74 R52.1 | 43.05,62.74 arc90 43.81,61.98 R55.1
N$96
  Top 0.178: R54.2 48.51,63.63 arc-90 48.77,63.37 R56.2 50.08,63.46 arc-90 50.16,63.37 | C45.2 50.16,63.37 | 50.16,63.37 arc90 50.55,62.99 52.2,62.99 52.2,62.93 IC12.49
N$97
  Top 0.178: R55.2 48.51,61.98 arc-90 48.77,61.72 | 48.77,61.72 R56.1 | 48.77,61.72 arc-90 48.81,61.76 C45.1 50.16,61.85 arc-90 50.55,62.23 52.2,62.23 arc90 52.32,62.36 52.3,62.36 IC12.50
N$98
  Top 0.178: R52.2 43.05,64.52 42.33,65.24 R53.2 41.78,65.28 41.53,65.53 IC11.10 40.13,67.18 C44.2 40.17,68.41 40.13,68.45 | L15.2 40.17,68.49 40.13,68.45 | 40.13,68.45 C43.1 | R48.2 R50.2 | R48.2 35.81,68.71 | R48.2 35.81,68.96 36.58,69.72 L15.2 | L15.2 40.26,69.72
N$99  (via drill 0.51)
  Top 0.178: C55.2 51.31,59.94 52.32,60.96 | L17.1 55.33,72.56 55.37,72.52 C54.2 55.37,70.74 55.5,70.61 55.5,70.58 IC12.37 55.4,70.61 55.5,70.48 | IC12.36 55.6,70.58 55.5,70.48 | IC12.42 53.17,67.48 53.59,67.06 v53.59,66.8 53.59,66.55 53.23,66.18 IC12.44 | 52.32,60.96 52.3,60.96 IC12.52 | v52.45,60.13 52.45,60.83 52.32,60.96 | 55.5,70.48 55.5,69.47 v55.37,69.34
  Bottom 0.178: 54.86,66.8 v53.59,66.8 52.45,65.66 v52.45,60.13 | 54.86,66.8 C53.2 | v55.37,69.34 55.37,67.31 54.86,66.8
N$100
  Top 0.178: IC12.7 58.04,59.18 58.04,58 arc-90 C47.2
N$101
  Top 0.178: IC12.8 58.67,59.18 58.67,57.87 arc90 C46.2
N$102
  Top 0.178: C48.2 50.42,66.8 51.69,65.53 IC12.45 52.32,65.53
N$103
  Top 0.178: C49.2 arc90 50.29,64.9 52.29,64.9 arc-90 IC12.46
N$104  (via drill 0.51)
  Top 0.178: L16.1 61,57.49 59.94,58.55 IC12.10 59.95,60.7 v59.94,60.71 | v57.28,60.71 57.35,60.63 IC12.6 IC12.5 | IC12.2 54.75,60.69 v54.74,60.71
  Bottom 0.178: 57.02,61.85 C50.2 | 57.02,61.85 56.98,61.89 C52.2 v54.74,60.71 | 59.82,61.85 C51.2 | 57.02,61.85 59.82,61.85 | 57.02,61.85 57.02,60.96 v57.28,60.71 | 59.82,61.85 59.82,60.83 v59.94,60.71
N$105
  Top 0.178: 0,1.27 0,0 1.27,0
N$106
  Top 0.178: IC12.30 59.95,73.54 arc-90 60.2,73.79 63.75,73.79 63.72,73.79 R61.1A
N$107
  Top 0.178: IC12.29 60.6,72.79 arc-90 60.83,73.03 63.75,73.03 63.75,73.04 R61.2A
N$108
  Top 0.178: IC12.28 61.25,71.92 arc-90 61.59,72.26 63.75,72.26 63.75,72.24 R61.3A
N$109
  Top 0.178: IC12.27 arc90 61.98,70.66 61.98,71.25 arc-90 62.23,71.5 63.75,71.5 63.72,71.5 R61.4A
N$110
  Top 0.178: IC12.26 66.6,68.78 arc-90 66.8,68.58 66.8,67.82 arc90 67.06,67.56 68.07,67.56 arc-180 68.03,67.56 R62.1A
N$111
  Top 0.178: IC12.25 65.98,68.13 arc-90 66.29,67.82 66.29,67.06 arc90 66.55,66.8 68.07,66.8 68.07,66.82 R62.2A
N$112
  Top 0.178: IC12.20 65.9,64.88 arc90 66.29,65.28 66.29,65.79 arc-90 66.55,66.04 68.07,66.04 68.07,66.02 R62.3A
N$113
  Top 0.178: IC12.19 66.52,64.23 arc90 66.8,64.52 66.8,65.02 arc-90 67.06,65.28 68.07,65.28 68.03,65.28 R62.4A
N$114
  Top 0.178: R63.1A 68.03,63.5 68.07,63.5 arc90 67.99,63.58 IC12.18
N$115
  Top 0.178: R63.2A 68.07,62.76 68.07,62.74 arc90 67.88,62.93 IC12.17
N$116
  Top 0.178: IC12.16 66.37,62.28 arc-90 66.55,62.1 66.55,61.98 arc90 66.67,61.85 67.82,61.85 arc90 67.94,61.98 67.94,61.96 R63.3A
N$117
  Top 0.178: IC12.15 66,61.63 arc-90 66.17,61.47 66.17,61.34 arc90 66.42,61.09 68.07,61.09 68.03,61.09 R63.4A
N$118
  Top 0.178: R33.2 17.53,71.12 16.76,71.88 14.61,71.88 14.61,74.68 IC8.7
N$119
  Top 0.178: C33.2 IC8.6
N$120
  Top 0.178: IC12.14 65.51,60.98 arc-90 65.79,60.71 65.79,59.69 arc90 66.04,59.44 67.56,59.44 arc-90 67.82,59.18 R64.1
N$121
  Top 0.178: TP4.TP 100.71,109.6 arc90 100.33,110.24 arc-90 99.82,110.74 IC17.4 99.82,112.27
N$122
  Top 0.178: R65.W R65.CW 29.21,24.13 29.21,25.15 32,27.94 NTC-.TP
  Bottom 0.178: R65.CW 27.94,21.59 Q1.1
N$123
  Bottom 0.178: 0,1.27 0,0 1.27,0
N$124
  Bottom 0.178: 0,139.45 0,140.72 1.27,140.72
N$125
  Top 0.178: 1.27,140.72 0,140.72 0,139.45
N$126
  Top 0.178: 165.61,140.72 166.88,140.72 166.88,139.45
N$127
  Bottom 0.178: 165.61,140.72 166.88,140.72 166.88,139.45
ORA  (via drill 0.51)
  Top 0.178: v104.65,89.79 104.52,89.92 103.76,89.92 IC16.70 | R32.2 70.1,97.03 74.55,97.03 74.55,93.47 76.58,91.44 v76.58,88.65
  Bottom 0.178: v104.65,89.79 100.84,85.98 98.68,85.98 98.3,85.6 85.22,85.6 84.84,85.98 76.71,85.98 76.71,88.27 v76.58,88.65
ORB
  Top 0.178: R64.2 70.1,59.69 78.36,59.69 78.36,75.31 80.55,77.5 IC16.136

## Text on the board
Top: Coincidence Timer | "PhotoFinish" | Rev:A Jan'08 | University of Toronto A.Steinberg Labs
Document: BNCs on | Top or | Bottom
tDocu: Coincidence Timer | "PhotoFinish" | A.Stummer Jan 2008 | .brd | A | 0.007"(0.178mm) | (0.025"(1mm)) | 0.007"(0.178mm) | 0.005"(0.127mm) | (0.01"(0.254mm)) | Power widths vary according to location and load. | Placement grid used haphazardly, sometimes 0.125mm. | Fits case Hammond 1598C.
